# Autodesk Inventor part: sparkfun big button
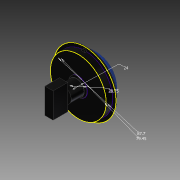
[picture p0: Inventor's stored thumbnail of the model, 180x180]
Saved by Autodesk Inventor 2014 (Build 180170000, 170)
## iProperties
Created: 2013-07
Part Number: sparkfun big button
Material: Generic
Document SubType Name: Modeling
Designer: Trip
Density: 1 g/cm^3
Appearance: Default
Author: Trip
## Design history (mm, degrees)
sketch "Sketch1"
  geometry: C1 r 49.125 at (0, 0); C2 r 12.925 at (0, 0); 1 further point
  constraints: 2 centre point, 2 coincident
  dimensions: "d0" = 98.25 diameter of C1; "d6" = 25.85 diameter of C2
extrude "Extrusion1" new body sketch "Sketch1" distance "d1" = 17.6; taper "d2" = 0 deg
sketch "Sketch2"
  geometry: C1 r 49.125 at (0, 0) reference; C2 r 45.625 at (0, 0)
  constraints: 1 centre point
  dimensions: "d3" = 3.5 radial gap between concentric circles of C1 C2
extrude "Extrusion2" cut sketch "Sketch2" distance "d4" = 12.6; taper "d5" = 0 deg
extrude "Extrusion3" cut sketch "Sketch1" stored distance "d7" = 12.6; taper "d8" = 0 deg
sketch "Sketch3"
  geometry: C1 r 49.125 at (0, 0) reference; C2 r 39.725 at (0, 0); C3 r 43.85 at (0, 0)
  constraints: 2 centre point, 2 coincident
  dimensions: "d9" = 79.45 diameter of C2; "d10" = 87.7 diameter of C3
extrude "Extrusion4" new body sketch "Sketch3" distance "d11" = 1.3; taper "d12" = 0 deg
extrude "Extrusion5" join sketch "Sketch3" distance "d13" = 6.75; taper "d14" = 0 deg
loft "Loft1" dims "d15" = 0, "d16" = 90 deg, "d17" = 0, "d18" = 90 deg
  node "Edges1"
  node "Edges2"
extrude "Extrusion6" join sketch "Sketch3" distance "d19" = 10.25; taper "d20" = 0 deg
workplane "Work Plane1"
extrude "Extrusion7" new body sketch "Sketch3" stored distance "d22" = 10.25; taper "d23" = 0 deg
sketch "Sketch5"
  geometry: L1 (-39.725, 28.35)-(39.725, 28.35) reference; L2 (0, 28.35)-(0, 48.35); L3 (0, 28.35)-(39.725, 28.35); A1 r 49.452 centre (0, -1.102) between (39.725, 28.35) and (0, 48.35); 1 further point
  constraints: 4 end point, 2 perpendicular, 2 point on circle, 1 centre point, 1 line through centre, 1 midpoint
  dimensions: "d25" = 20 distance of L2.start L2.end
revolve "Revolution2" sketch "Sketch5" stored, may be unused: angle "d26" = 90 deg
sketch "Sketch6"
  geometry: C1 r 43.85 at (0, 0) reference; C2 r 14.375 at (0, 0); C3 r 12 at (0, 0)
  constraints: 2 centre point, 2 coincident
  dimensions: "d27" = 28.75 diameter of C2; "d33" = 24 diameter of C3
extrude "Extrusion8" join sketch "Sketch6" distance "d28" = 2.75; taper "d29" = 0 deg
sketch "Sketch7"
  geometry: L1 (-2.998, 43.747)-(2.998, 43.747); A1 r 3 centre (0, 43.85) between (2.998, 43.747) and (-2.998, 43.747); A2 r 43.85 centre (0, 0) between (2.998, 43.747) and (-2.998, 43.747) reference; 1 further point
  constraints: 4 point on circle, 2 end point, 1 centre point, 1 coincident, 1 horizontal
  dimensions: "d30" = 3 radius of A1
extrude "Extrusion9" join sketch "Sketch7" distance "d31" = 2.75; taper "d32" = 0 deg
extrude "Extrusion10" join sketch "Sketch6" distance "d34" = 23; taper "d35" = 0 deg
chamfer "Chamfer1" distance "d36" = 2; stored, may be unused: second distance "d37" = 2, angle "d38" = 45 deg
sketch "Sketch8"
  geometry: L1 (-6.5, -20)-(6.5, -20); L2 (6.5, -20)-(6.5, 20); L3 (6.5, 20)-(-6.5, 20); L4 (-6.5, 20)-(-6.5, -20); L5 (-6.5, -20)-(6.5, 20); L6 (6.5, -20)-(-6.5, 20); C1 r 12 at (0, 0) reference
  constraints: 12 end point, 2 midpoint, 2 parallel, 1 horizontal, 1 perpendicular
  dimensions: "d39" = 13 distance of L3.end L2.end; "d40" = 40 distance of L2.end L1.end
extrude "Extrusion11" join sketch "Sketch8" distance "d41" = 23; taper "d42" = 0 deg
body "Solid1"
body "Solid2"
body "Solid3"
other parameters: "d21" = 4
